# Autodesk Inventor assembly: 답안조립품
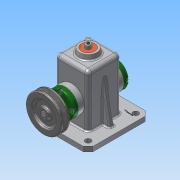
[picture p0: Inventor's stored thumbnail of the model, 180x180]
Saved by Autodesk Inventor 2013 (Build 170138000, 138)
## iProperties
Created: 2016-02
Part Number: 답안조립품
Document SubType Name: Assembly
Designer: user-11
Author: user-11
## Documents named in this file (16)
- C:\Users\user-11\Desktop\460211V1007\답안조립품.iam
- C:\Users\user-11\Desktop\460211V1007\본체.ipt
- C:\Users\user-11\Desktop\460211V1007\앞커버.ipt
- C:\Users\user-11\Desktop\460211V1007\뒤커버.ipt
- C:\Users\user-11\Desktop\460211V1007\베어링 12 x 32 x 10.ipt
- C:\Users\user-11\Desktop\460211V1007\오일실 12 25 7.ipt
- C:\Users\user-11\Desktop\460211V1007\편심축.ipt
- C:\Users\user-11\Desktop\460211V1007\링크.ipt
- C:\Users\user-11\Desktop\460211V1007\슬라이드.ipt
- C:\Users\user-11\Desktop\460211V1007\핀 5 x 18.ipt
- C:\Users\user-11\Desktop\460211V1007\고정핀 1.2 x 10.ipt
- C:\Users\user-11\Desktop\460211V1007\부시.ipt
- C:\Users\user-11\Desktop\460211V1007\키 4 x 4 x 10.ipt
- C:\Users\user-11\Desktop\460211V1007\V벨트풀리.ipt
- C:\Users\user-11\Desktop\460211V1007\멈춤나사 M3x8.ipt
- C:\Users\user-11\Desktop\460211V1007\볼트 M4 x 12.ipt
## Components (11 placed, 4 different names)
1. 핀 5 x 18:1
2. 고정핀 1.2 x 10:1
3. V벨트풀리:1 — 각도:2
4. ISO 4762 M4 x 12:1
5. ISO 4762 M4 x 12:2
6. ISO 4762 M4 x 12:3
7. ISO 4762 M4 x 12:4
8. ISO 4762 M4 x 12:5
9. ISO 4762 M4 x 12:6
10. ISO 4762 M4 x 12:7
11. ISO 4762 M4 x 12:8
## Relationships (1: Angle 1)
- 각도:2 [Angle]: V벨트풀리:1
